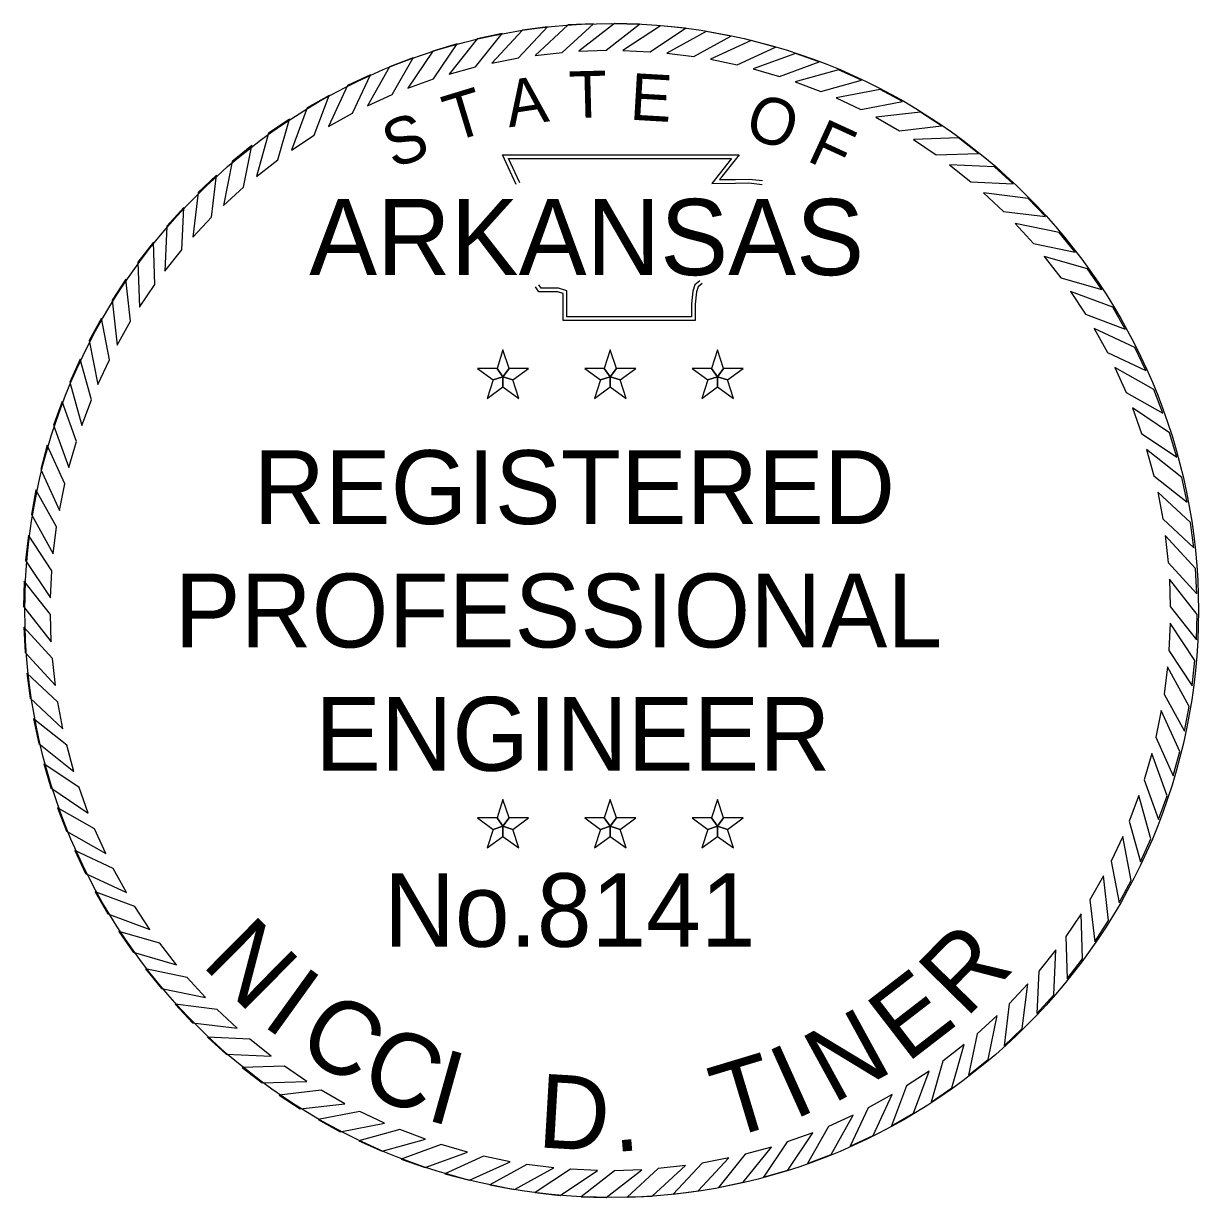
# Model space of a CAD drawing. Extents: x 0 to 762217, y -63 to 1662473.
# Drawn here: x 1782.2 to 1902.4, y 908.4 to 1028.4 of the extents above; entities that cross this region are included whole.
import ezdxf

# ---------------------------------------------------------------- set-up
doc = ezdxf.new("R2010")
doc.units = 0
for name, color, linetype in [('G-ANNO-SYMB', 7, 'Continuous'), ('G-ANNO-TEXT', 7, 'Continuous'), ('G-No Plot-Stamp', 7, 'Continuous')]:
    doc.layers.add(name, color=color, linetype=linetype)

msp = doc.modelspace()

# ---------------------------------------------------------------- linework, layer by layer
at = {"layer": 'G-ANNO-SYMB'}
for points in [[(1831.17, 1027.32), (1828.64, 1026.79), (1825.78, 1023.19), (1828.47, 1023.93)], [(1835.83, 1028.01), (1833.27, 1027.68), (1830.13, 1024.31), (1832.87, 1024.84)], [(1840.53, 1028.33), (1837.95, 1028.2), (1834.56, 1025.09), (1837.33, 1025.4)], [(1845.24, 1028.28), (1842.66, 1028.35), (1839.04, 1025.52), (1841.82, 1025.61)], [(1849.93, 1027.86), (1847.37, 1028.13), (1843.53, 1025.6), (1846.32, 1025.46)], [(1854.58, 1027.07), (1852.04, 1027.55), (1848.02, 1025.32), (1850.78, 1024.97)], [(1826.57, 1026.27), (1824.1, 1025.54), (1821.53, 1021.73), (1824.15, 1022.68)], [(1859.15, 1025.92), (1856.65, 1026.6), (1852.47, 1024.69), (1855.2, 1024.12)], [(1822.08, 1024.86), (1819.67, 1023.94), (1817.4, 1019.94), (1819.94, 1021.09)], [(1863.61, 1024.42), (1861.18, 1025.29), (1856.86, 1023.71), (1859.54, 1022.94)], [(1867.94, 1022.57), (1865.59, 1023.62), (1861.16, 1022.4), (1863.77, 1021.41)], [(1817.71, 1023.11), (1815.37, 1022), (1813.43, 1017.83), (1815.87, 1019.18)], [(1872.12, 1020.39), (1869.85, 1021.62), (1865.34, 1020.74), (1867.86, 1019.56)], [(1813.49, 1021.01), (1811.25, 1019.73), (1809.64, 1015.42), (1811.97, 1016.95)], [(1876.11, 1017.88), (1873.95, 1019.29), (1869.38, 1018.77), (1871.8, 1017.39)], [(1809.44, 1018.59), (1807.31, 1017.14), (1806.05, 1012.72), (1808.25, 1014.43)], [(1879.89, 1015.07), (1877.85, 1016.65), (1873.25, 1016.49), (1875.56, 1014.92)], [(1805.6, 1015.87), (1803.59, 1014.25), (1802.68, 1009.74), (1804.74, 1011.62)], [(1801.99, 1012.84), (1800.11, 1011.07), (1799.55, 1006.51), (1801.46, 1008.54)], [(1883.44, 1011.97), (1881.53, 1013.7), (1876.93, 1013.91), (1879.11, 1012.16)], [(1886.74, 1008.61), (1884.96, 1010.48), (1880.4, 1011.04), (1882.43, 1009.14)], [(1798.62, 1009.55), (1796.89, 1007.64), (1796.69, 1003.04), (1798.43, 1005.22)], [(1889.76, 1004.99), (1888.14, 1007), (1883.63, 1007.92), (1885.51, 1005.86)], [(1795.52, 1006), (1793.95, 1003.96), (1794.11, 999.36), (1795.67, 1001.67)], [(1892.49, 1001.15), (1891.03, 1003.28), (1886.61, 1004.55), (1888.32, 1002.35)], [(1792.71, 1002.22), (1791.3, 1000.06), (1791.82, 995.49), (1793.2, 997.91)], [(1894.9, 997.11), (1893.62, 999.35), (1889.31, 1000.96), (1890.84, 998.63)], [(1790.21, 998.23), (1788.97, 995.96), (1789.85, 991.45), (1791.04, 993.97)], [(1897, 992.89), (1895.89, 995.22), (1891.72, 997.16), (1893.07, 994.72)], [(1831.27, 992.24), (1831.89, 993.09), (1831.27, 994.99), (1830.66, 993.09)], [(1842.24, 992.24), (1842.86, 993.09), (1842.24, 994.99), (1841.63, 993.09)], [(1853.21, 992.24), (1853.83, 993.09), (1853.21, 994.99), (1852.6, 993.09)], [(1788.02, 994.05), (1786.97, 991.7), (1788.2, 987.27), (1789.18, 989.87)], [(1831.27, 992.24), (1830.66, 993.09), (1828.66, 993.09), (1830.27, 991.92)], [(1831.27, 992.24), (1832.27, 991.92), (1833.88, 993.09), (1831.89, 993.09)], [(1842.24, 992.24), (1841.63, 993.09), (1839.63, 993.09), (1841.25, 991.92)], [(1842.24, 992.24), (1843.24, 991.92), (1844.85, 993.09), (1842.86, 993.09)], [(1853.21, 992.24), (1852.6, 993.09), (1850.61, 993.09), (1852.22, 991.92)], [(1853.21, 992.24), (1854.21, 991.92), (1855.82, 993.09), (1853.83, 993.09)], [(1898.75, 988.52), (1897.83, 990.93), (1893.83, 993.19), (1894.98, 990.65)], [(1831.27, 992.24), (1830.27, 991.92), (1829.66, 990.03), (1831.27, 991.2)], [(1831.27, 992.24), (1831.27, 991.2), (1832.88, 990.03), (1832.27, 991.92)], [(1842.24, 992.24), (1841.25, 991.92), (1840.63, 990.03), (1842.24, 991.2)], [(1842.24, 992.24), (1842.24, 991.2), (1843.85, 990.03), (1843.24, 991.92)], [(1853.21, 992.24), (1852.22, 991.92), (1851.6, 990.03), (1853.21, 991.2)], [(1853.21, 992.24), (1853.21, 991.2), (1854.83, 990.03), (1854.21, 991.92)], [(1786.18, 989.72), (1785.31, 987.29), (1786.88, 982.97), (1787.66, 985.64)], [(1900.16, 984.02), (1899.43, 986.5), (1895.62, 989.07), (1896.57, 986.45)], [(1784.67, 985.25), (1784, 982.76), (1785.91, 978.58), (1786.47, 981.31)], [(1901.21, 979.43), (1900.68, 981.95), (1897.08, 984.82), (1897.82, 982.13)], [(1783.52, 980.69), (1783.05, 978.15), (1785.28, 974.13), (1785.63, 976.89)], [(1901.9, 974.77), (1901.57, 977.33), (1898.21, 980.46), (1898.73, 977.72)], [(1782.74, 976.04), (1782.46, 973.47), (1785, 969.64), (1785.13, 972.42)], [(1902.22, 970.07), (1902.09, 972.64), (1898.98, 976.03), (1899.29, 973.26)], [(1782.32, 971.35), (1782.24, 968.77), (1785.07, 965.14), (1784.99, 967.93)], [(1902.17, 965.36), (1902.24, 967.93), (1899.41, 971.56), (1899.5, 968.77)], [(1782.27, 966.64), (1782.4, 964.06), (1785.5, 960.67), (1785.2, 963.44)], [(1901.75, 960.66), (1902.02, 963.23), (1899.49, 967.06), (1899.36, 964.28)], [(1900.96, 956.02), (1901.44, 958.55), (1899.21, 962.58), (1898.86, 959.81)], [(1782.59, 961.94), (1782.92, 959.38), (1786.28, 956.24), (1785.76, 958.98)], [(1899.81, 951.45), (1900.49, 953.94), (1898.58, 958.12), (1898.02, 955.39)], [(1783.27, 957.28), (1783.8, 954.75), (1787.4, 951.89), (1786.67, 954.58)], [(1898.31, 946.98), (1899.18, 949.41), (1897.6, 953.74), (1896.83, 951.06)], [(1784.32, 952.68), (1785.05, 950.21), (1788.86, 947.64), (1787.92, 950.26)], [(1896.46, 942.65), (1897.52, 945.01), (1896.29, 949.44), (1895.3, 946.83)], [(1785.73, 948.19), (1786.65, 945.78), (1790.65, 943.51), (1789.51, 946.05)], [(1831.27, 946.3), (1831.89, 947.15), (1831.27, 949.04), (1830.66, 947.15)], [(1842.24, 946.3), (1842.86, 947.15), (1842.24, 949.04), (1841.63, 947.15)], [(1853.21, 946.3), (1853.83, 947.15), (1853.21, 949.04), (1852.6, 947.15)], [(1831.27, 946.3), (1830.66, 947.15), (1828.66, 947.15), (1830.27, 945.98)], [(1831.27, 946.3), (1832.27, 945.98), (1833.88, 947.15), (1831.89, 947.15)], [(1842.24, 946.3), (1841.63, 947.15), (1839.63, 947.15), (1841.25, 945.98)], [(1842.24, 946.3), (1843.24, 945.98), (1844.85, 947.15), (1842.86, 947.15)], [(1853.21, 946.3), (1852.6, 947.15), (1850.61, 947.15), (1852.22, 945.98)], [(1853.21, 946.3), (1854.21, 945.98), (1855.82, 947.15), (1853.83, 947.15)], [(1831.27, 946.3), (1830.27, 945.98), (1829.66, 944.08), (1831.27, 945.25)], [(1831.27, 946.3), (1831.27, 945.25), (1832.88, 944.08), (1832.27, 945.98)], [(1842.24, 946.3), (1841.25, 945.98), (1840.63, 944.08), (1842.24, 945.25)], [(1842.24, 946.3), (1842.24, 945.25), (1843.85, 944.08), (1843.24, 945.98)], [(1853.21, 946.3), (1852.22, 945.98), (1851.6, 944.08), (1853.21, 945.25)], [(1853.21, 946.3), (1853.21, 945.25), (1854.83, 944.08), (1854.21, 945.98)], [(1894.28, 938.48), (1895.51, 940.74), (1894.64, 945.26), (1893.45, 942.73)], [(1787.49, 943.82), (1788.59, 941.48), (1792.76, 939.54), (1791.42, 941.98)], [(1891.77, 934.49), (1893.18, 936.65), (1892.66, 941.22), (1891.28, 938.79)], [(1789.58, 939.59), (1790.87, 937.36), (1795.17, 935.75), (1793.64, 938.08)], [(1888.96, 930.7), (1890.54, 932.75), (1890.38, 937.34), (1888.81, 935.04)], [(1792, 935.55), (1793.46, 933.42), (1797.88, 932.15), (1796.17, 934.36)], [(1885.87, 927.15), (1887.6, 929.07), (1887.8, 933.66), (1886.05, 931.49)], [(1794.73, 931.71), (1796.35, 929.7), (1800.85, 928.79), (1798.98, 930.85)], [(1882.5, 923.86), (1884.37, 925.63), (1884.93, 930.2), (1883.03, 928.16)], [(1797.75, 928.1), (1799.52, 926.22), (1804.09, 925.66), (1802.05, 927.57)], [(1878.88, 920.84), (1880.89, 922.46), (1881.81, 926.96), (1879.75, 925.09)], [(1801.05, 924.73), (1802.96, 923), (1807.55, 922.8), (1805.38, 924.54)], [(1875.04, 918.11), (1877.17, 919.57), (1878.44, 923.99), (1876.24, 922.28)], [(1804.59, 921.63), (1806.64, 920.06), (1811.23, 920.22), (1808.93, 921.78)], [(1871, 915.69), (1873.24, 916.98), (1874.85, 921.28), (1872.52, 919.75)], [(1808.38, 918.82), (1810.54, 917.41), (1815.11, 917.93), (1812.68, 919.31)], [(1866.78, 913.6), (1869.11, 914.7), (1871.05, 918.87), (1868.61, 917.53)], [(1812.37, 916.32), (1814.63, 915.08), (1819.15, 915.96), (1816.62, 917.14)], [(1862.41, 911.84), (1864.82, 912.76), (1867.08, 916.76), (1864.54, 915.61)], [(1816.54, 914.13), (1818.9, 913.08), (1823.33, 914.31), (1820.72, 915.29)], [(1857.91, 910.43), (1860.39, 911.16), (1862.96, 914.97), (1860.34, 914.03)], [(1820.87, 912.28), (1823.31, 911.42), (1827.63, 912.99), (1824.95, 913.77)], [(1853.32, 909.38), (1855.84, 909.91), (1858.71, 913.51), (1856.02, 912.78)], [(1825.34, 910.78), (1827.83, 910.11), (1832.02, 912.01), (1829.29, 912.58)], [(1848.66, 908.69), (1851.22, 909.03), (1854.35, 912.39), (1851.62, 911.87)], [(1829.91, 909.63), (1832.44, 909.16), (1836.47, 911.39), (1833.7, 911.73)], [(1834.55, 908.85), (1837.12, 908.57), (1840.95, 911.11), (1838.17, 911.24)], [(1839.25, 908.43), (1841.83, 908.35), (1845.45, 911.18), (1842.66, 911.09)], [(1843.96, 908.37), (1846.53, 908.5), (1849.93, 911.61), (1847.15, 911.3)]]:
    msp.add_lwpolyline(points, close=True, dxfattribs=at)
for points in [[(1832.63, 1011.9), (1831.23, 1014.93), (1855.43, 1014.94), (1853.41, 1012.4), (1855.05, 1012.42), (1856.43, 1012.44), (1857.8, 1012.29)], [(1832.98, 1012.06), (1831.83, 1014.55), (1854.64, 1014.56), (1852.61, 1012.01), (1855.06, 1012.04), (1856.41, 1012.06), (1857.76, 1011.91)], [(1851.38, 1002.05), (1850.87, 1001.64), (1850.69, 1000.99), (1850.55, 999.69), (1850.55, 998.38), (1837.81, 998.38), (1837.81, 1000.25), (1837.81, 1001.04), (1836.93, 1001.3), (1835.16, 1001.3), (1834.93, 1001.65)], [(1851.62, 1001.76), (1851.21, 1001.42), (1851.07, 1000.92), (1850.93, 999.66), (1850.93, 997.99), (1837.42, 997.99), (1837.42, 1000.25), (1837.42, 1000.75), (1836.87, 1000.92), (1834.95, 1000.92), (1834.61, 1001.44)]]:
    msp.add_lwpolyline(points, dxfattribs=at)
at = {"layer": 'G-No Plot-Stamp'}
msp.add_circle((1842.38, 968.35), 60, dxfattribs=at)

# ---------------------------------------------------------------- texts
at = {"layer": 'G-ANNO-TEXT'}
for s, height, rotation, p in [('A', 4.77, 8.6788, (1831.89, 1017.73)), ('T', 4.77, 1.4789, (1838.06, 1018.68)), ('E', 4.77, 356.672, (1844.17, 1018.53)), ('T', 4.77, 16.9015, (1826.1, 1016.21)), ('O', 4.77, 341.2218, (1855.76, 1016.89)), ('S', 4.77, 19.7726, (1820.03, 1013.49)), ('F', 4.77, 335.3628, (1862.19, 1014.38)), ('N', 7.54, 315.2676, (1800.33, 932.16)), ('R', 7.54, 45.478, (1878.58, 926.57)), ('I', 7.54, 324.2141, (1806.46, 926.09)), ('E', 7.54, 37.6498, (1872.55, 922.01)), ('C', 7.54, 328.6873, (1809.87, 923.42)), ('N', 7.54, 28.7033, (1864.98, 917.86)), ('C', 7.54, 336.5155, (1816.29, 919.43)), ('I', 7.54, 24.2301, (1860.97, 916.24)), ('I', 7.54, 344.3437, (1823.19, 916.35)), ('T', 7.54, 16.7747, (1854.05, 914.25)), ('D', 7.54, 356.6451, (1834.71, 913.49)), ('.', 7.54, 4.846, (1842.61, 912.98))]:
    msp.add_text(s, height=height, rotation=rotation, dxfattribs=at).set_placement(p)
for s, height, p in [('ARKANSAS', 7.791, (1811.45, 1002.63)), ('REGISTERED', 7.543, (1805.78, 977.19)), ('PROFESSIONAL', 7.543, (1797.7, 964.58)), ('ENGINEER', 7.543, (1812.07, 951.97)), ('No.8141', 7.513, (1819.1, 933.98))]:
    msp.add_text(s, height=height, dxfattribs=at).set_placement(p)

doc.saveas('drawing.dxf')
